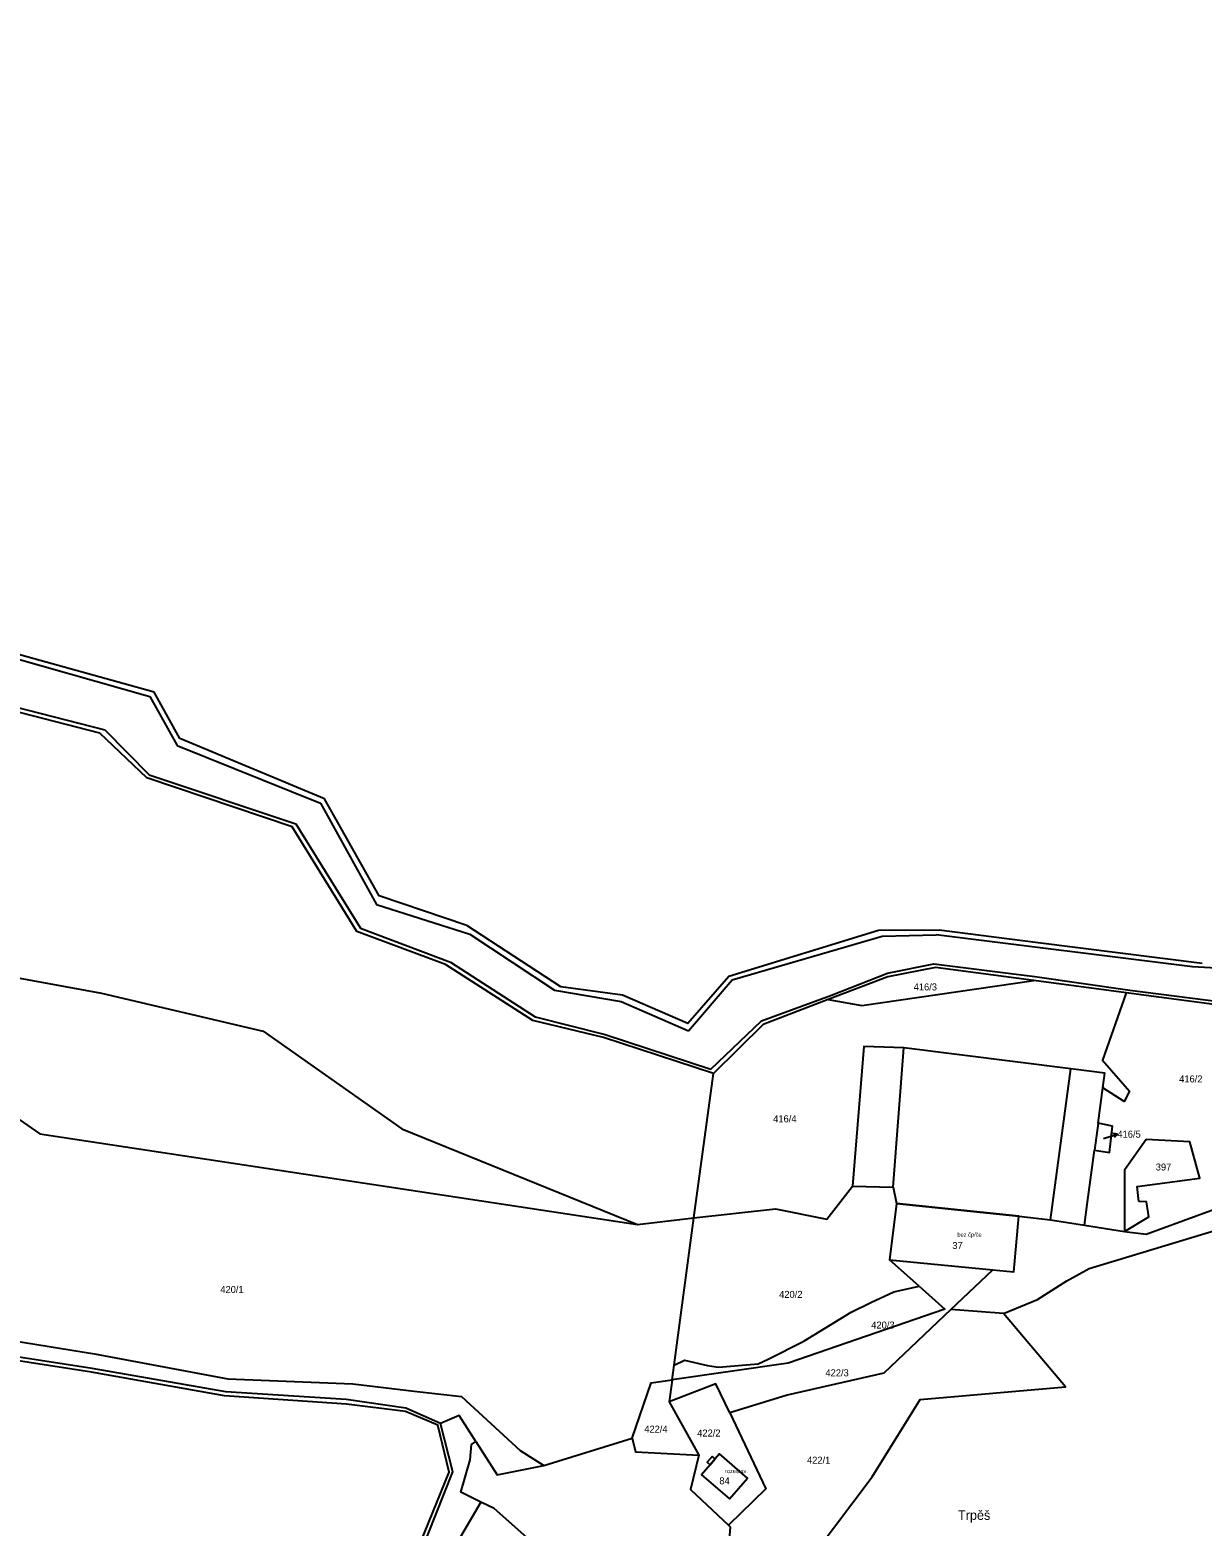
# Model space of a CAD drawing. Extents: x -880531 to -877616, y -1023932 to -1021350.
# Drawn here: x -879800.4 to -879514.7, y -1022591 to -1022226.3 of the extents above; entities that cross this region are included whole.
import ezdxf

# ---------------------------------------------------------------- set-up
doc = ezdxf.new("R2010")
doc.units = 0
for name, color, linetype in [('Definiční body', 7, 'Continuous'), ('Hranice parcel', 7, 'Continuous'), ('Parcelní čísla', 7, 'Continuous'), ('Polygon budovy', 7, 'Continuous'), ('Pop  PČ popisy', 7, 'Continuous'), ('Vnitřní kresba', 7, 'Continuous')]:
    doc.layers.add(name, color=color, linetype=linetype)

msp = doc.modelspace()

# ---------------------------------------------------------------- linework, layer by layer
at = {"layer": 'Hranice parcel'}
for p, q in [((-879763.86, -1022398.98), (-879770.1, -1022387.72)), ((-879728.59, -1022413.68), (-879763.86, -1022398.98)), ((-879670.97, -1022459.53), (-879693.89, -1022444.57)), ((-879578.79, -1022445.71), (-879593.51, -1022445.8)), ((-879554.59, -1022448.77), (-879578.79, -1022445.71)), ((-879514.65, -1022453.82), (-879554.59, -1022448.77)), ((-879555.71, -1022458), (-879579.68, -1022454.82)), ((-879655.97, -1022461.57), (-879670.97, -1022459.53)), ((-879533.14, -1022460.99), (-879555.71, -1022458)), ((-879638.53, -1022515.87), (-879633.8, -1022480.63)), ((-879539.96, -1022492.77), (-879538.83, -1022484.18)), ((-879539.96, -1022492.77), (-879540.85, -1022499.34)), ((-879652.28, -1022517.43), (-879638.53, -1022515.87)), ((-879643.35, -1022551.75), (-879638.53, -1022515.87)), ((-879583.67, -1022532.48), (-879590.9, -1022526.1)), ((-879590.9, -1022526.1), (-879565.68, -1022528.5)), ((-879575.88, -1022538.17), (-879565.68, -1022528.5)), ((-879563.05, -1022539.12), (-879575.88, -1022538.17)), ((-879643.83, -1022555.3), (-879643.35, -1022551.75)), ((-879643.83, -1022555.3), (-879644.55, -1022560.66)), ((-879644.55, -1022560.66), (-879637.31, -1022573.67)), ((-879675.16, -1022576.16), (-879653.62, -1022569.51)), ((-879690.46, -1022585.1), (-879713.01, -1022623.35))]:
    msp.add_line(p, q, dxfattribs=at)
for points in [[(-879633.8, -1022480.63), (-879660.6, -1022471.88), (-879677.81, -1022467.72), (-879699.12, -1022454.05), (-879720.69, -1022446.04), (-879736.48, -1022420.52), (-879771.92, -1022408.58), (-879783.4, -1022397.72), (-879810.92, -1022390.65), (-879838.37, -1022390.91), (-879846.45, -1022372.72), (-879862.92, -1022363.84), (-879883.64, -1022339.68), (-879913.23, -1022324.87), (-879930.34, -1022275.22), (-879914.25, -1022226.31)], [(-879770.1, -1022387.72), (-879811.18, -1022376.32), (-879830.38, -1022382.07), (-879836.8, -1022364.1)], [(-879693.89, -1022444.57), (-879715.3, -1022437.37), (-879728.59, -1022413.68)], [(-879593.51, -1022445.8), (-879630.07, -1022456.98), (-879639.99, -1022468.49), (-879655.97, -1022461.57)], [(-879579.68, -1022454.82), (-879591.23, -1022457.13), (-879605.78, -1022462.66)], [(-879605.78, -1022462.66), (-879597.6, -1022464.07), (-879555.71, -1022458)], [(-879847.14, -1022461.29), (-879797.97, -1022495.32), (-879652.28, -1022517.43)], [(-879605.78, -1022462.66), (-879621.67, -1022468.7), (-879633.8, -1022480.63)], [(-879533.14, -1022460.99), (-879538.93, -1022477.37), (-879532.34, -1022484.94), (-879533.66, -1022487.52), (-879538.83, -1022484.18)], [(-879490.51, -1022467.67), (-879510.53, -1022463.99), (-879533.14, -1022460.99)], [(-879538.83, -1022484.18), (-879538.35, -1022480.6), (-879546.67, -1022479.54), (-879587.34, -1022474.44), (-879597.1, -1022474.1), (-879599.9, -1022508.1)], [(-879540.85, -1022499.34), (-879537.2, -1022499.95), (-879536.53, -1022493.49), (-879539.96, -1022492.77)], [(-879543.35, -1022517.62), (-879542.66, -1022512.62), (-879540.85, -1022499.34)], [(-879530.05, -1022511.88), (-879530.46, -1022508.22), (-879515.2, -1022506.16), (-879517.67, -1022497.29), (-879528.26, -1022496.74), (-879533.58, -1022504.22), (-879533.58, -1022519.17), (-879527.61, -1022515.57), (-879528.19, -1022511.94), (-879530.05, -1022511.88)], [(-879638.53, -1022515.87), (-879618.62, -1022513.62), (-879606.17, -1022516.16), (-879599.9, -1022508.1)], [(-879599.9, -1022508.1), (-879589.98, -1022508.36), (-879589.13, -1022512.34), (-879590.9, -1022526.1)], [(-879563.05, -1022539.12), (-879554.81, -1022535.76), (-879547.63, -1022531.21), (-879542.21, -1022528.17), (-879482.3, -1022510.07)], [(-879543.35, -1022517.62), (-879533.58, -1022519.17), (-879528.32, -1022519.79), (-879503.43, -1022510.75)], [(-879565.68, -1022528.5), (-879560.58, -1022528.99), (-879559.36, -1022515.4), (-879551.61, -1022516.33), (-879543.35, -1022517.62)], [(-879583.67, -1022532.48), (-879577.35, -1022538.06), (-879615.55, -1022551.26), (-879643.83, -1022555.3)], [(-879643.35, -1022551.75), (-879640.86, -1022550.5), (-879635.23, -1022551.85), (-879632.56, -1022552.27), (-879622.84, -1022551.45), (-879620.41, -1022550.3), (-879611.78, -1022545.93), (-879600.23, -1022538.83), (-879595.39, -1022536.5), (-879589.77, -1022533.86), (-879583.67, -1022532.48)], [(-879841.96, -1022539.75), (-879784.65, -1022548.98), (-879752.14, -1022555.09), (-879721.69, -1022556.28), (-879706.73, -1022558.11), (-879695.24, -1022559.41), (-879680.86, -1022572.57), (-879675.16, -1022576.16)], [(-879575.88, -1022538.17), (-879592.27, -1022553.71), (-879615.81, -1022559.05), (-879629.81, -1022563.35)], [(-879623.38, -1022616.52), (-879595.05, -1022578.95), (-879583.42, -1022560.14), (-879547.99, -1022557.04), (-879563.05, -1022539.12)], [(-879700.32, -1022565.93), (-879708.74, -1022562.21), (-879723.29, -1022560.15), (-879752.61, -1022558.22), (-879785.23, -1022552.56), (-879842.49, -1022543.71), (-879866.35, -1022541.91), (-879881.1, -1022540.95)], [(-879653.62, -1022569.51), (-879648.95, -1022556.03), (-879643.83, -1022555.3)], [(-879629.81, -1022563.35), (-879633.16, -1022556.29), (-879644.55, -1022560.66)], [(-879691.7, -1022570.37), (-879695.74, -1022564.05), (-879700.32, -1022565.93)], [(-879629.81, -1022563.35), (-879621.04, -1022581.85), (-879630.14, -1022590.7)], [(-879713.01, -1022623.35), (-879707.48, -1022603.31), (-879697.33, -1022577.75), (-879700.32, -1022565.93)], [(-879690.46, -1022585.1), (-879695.33, -1022582.69), (-879693.09, -1022574.84), (-879692.78, -1022571.11), (-879691.7, -1022570.37)], [(-879691.7, -1022570.37), (-879686.53, -1022578.44), (-879675.16, -1022576.16)], [(-879653.62, -1022569.51), (-879652.78, -1022572.88), (-879637.31, -1022573.67)], [(-879637.31, -1022573.67), (-879639.41, -1022582.07), (-879630.14, -1022590.7)], [(-879625.5, -1022579.31), (-879632.31, -1022573.37), (-879633.35, -1022574.59), (-879634.07, -1022573.97), (-879635.33, -1022575.41), (-879634.6, -1022576.04), (-879636.67, -1022578.45), (-879629.84, -1022584.35), (-879625.5, -1022579.31)], [(-879664.81, -1022605.75), (-879667.6, -1022604.17), (-879687.23, -1022586.69), (-879690.46, -1022585.1)], [(-879630.14, -1022590.7), (-879629.68, -1022591.13), (-879630.98, -1022608.24), (-879627.75, -1022611.76)]]:
    msp.add_lwpolyline(points, dxfattribs=at)
at = {"layer": 'Polygon budovy'}
for points in [[(-879565.68, -1022528.5), (-879560.58, -1022528.99), (-879559.36, -1022515.4), (-879589.13, -1022512.34), (-879590.9, -1022526.1)], [(-879629.84, -1022584.35), (-879625.5, -1022579.31), (-879632.31, -1022573.37), (-879633.35, -1022574.59), (-879634.6, -1022576.04), (-879636.67, -1022578.45)]]:
    msp.add_lwpolyline(points, close=True, dxfattribs=at)
at = {"layer": 'Pop  PČ popisy'}
for p, q in [((-879538.17, -1022496.36), (-879535.316, -1022495.433)), ((-879535.316, -1022495.433), (-879536.423, -1022495.266)), ((-879535.316, -1022495.433), (-879536.114, -1022496.218)), ((-879538.69, -1022496.53), (-879538.17, -1022496.36))]:
    msp.add_line(p, q, dxfattribs=at)
at = {"layer": 'Vnitřní kresba'}
for p, q in [((-879771.18, -1022388.74), (-879764.55, -1022400.69)), ((-879764.55, -1022400.69), (-879729.54, -1022414.79)), ((-879729.54, -1022414.79), (-879715.91, -1022439.43)), ((-879715.91, -1022439.43), (-879693.14, -1022446.71)), ((-879693.14, -1022446.71), (-879672.54, -1022460.35)), ((-879517.02, -1022454.68), (-879579.49, -1022446.85)), ((-879831.44, -1022452.23), (-879783, -1022461.08)), ((-879783, -1022461.08), (-879743.51, -1022470.31)), ((-879672.54, -1022460.35), (-879656.27, -1022463.14)), ((-879656.27, -1022463.14), (-879639.9, -1022470.25)), ((-879743.51, -1022470.31), (-879709.78, -1022494.17)), ((-879589.98, -1022508.36), (-879587.34, -1022474.44)), ((-879551.61, -1022516.33), (-879546.67, -1022479.54)), ((-879709.78, -1022494.17), (-879652.28, -1022517.43)), ((-879589.13, -1022512.34), (-879559.36, -1022515.4)), ((-879634.6, -1022576.04), (-879633.35, -1022574.59))]:
    msp.add_line(p, q, dxfattribs=at)
for points in [[(-879912.42, -1022323.74), (-879882.14, -1022339.39), (-879861.47, -1022363.57), (-879845.41, -1022372.16), (-879837.93, -1022390.13), (-879810.43, -1022389.65), (-879782.15, -1022396.86), (-879771.34, -1022407.84), (-879735.56, -1022419.77), (-879719.82, -1022445.22), (-879697.88, -1022453.49), (-879677.21, -1022466.85), (-879660.2, -1022471.15), (-879634.44, -1022479.57)], [(-879831.15, -1022382.88), (-879811.34, -1022377.43), (-879771.18, -1022388.74)], [(-879639.9, -1022470.25), (-879629.21, -1022457.86), (-879592.66, -1022447.16), (-879579.49, -1022446.85)], [(-879634.44, -1022479.57), (-879622.04, -1022467.8), (-879605.03, -1022461.6), (-879591.35, -1022456.19), (-879580.07, -1022453.96), (-879555.42, -1022456.98), (-879532.25, -1022460.34), (-879509.99, -1022463.2), (-879489.48, -1022467.02)], [(-879461.76, -1022458.04), (-879478.09, -1022458.2), (-879481.7, -1022456.64), (-879517.02, -1022454.68)], [(-879714.02, -1022623.13), (-879708.26, -1022602.63), (-879698.24, -1022577.81), (-879700.94, -1022566.36), (-879708.89, -1022563.02), (-879723.21, -1022561.27), (-879752.94, -1022559.2), (-879785.38, -1022553.47), (-879842.62, -1022544.57)]]:
    msp.add_lwpolyline(points, dxfattribs=at)

# ---------------------------------------------------------------- texts
at = {"layer": 'Definiční body'}
for s, p in [('bez čp/če', (-879574.3, -1022520.44)), ('rozestav.', (-879630.98, -1022578.06))]:
    msp.add_text(s, height=1, dxfattribs=at).set_placement(p)
at = {"layer": 'Parcelní čísla'}
for s, p in [('416/3', (-879584.98, -1022460.41)), ('416/2', (-879520.25, -1022482.83)), ('416/4', (-879619.22, -1022492.54)), ('416/5', (-879535.31, -1022496.3)), ('397', (-879525.96, -1022504.3)), ('37', (-879575.55, -1022523.44)), ('420/1', (-879754, -1022534.14)), ('420/2', (-879617.76, -1022535.34)), ('420/3', (-879595.314, -1022542.81)), ('422/3', (-879606.48, -1022554.45)), ('422/4', (-879650.64, -1022568.18)), ('422/2', (-879637.74, -1022569.13)), ('422/1', (-879610.98, -1022575.75)), ('84', (-879632.34, -1022580.77))]:
    msp.add_text(s, height=1.7, dxfattribs=at).set_placement(p)
at = {"layer": 'Pop  PČ popisy'}
msp.add_text('Trpěš', height=2.3, dxfattribs=at).set_placement((-879574.156, -1022589.44))

doc.saveas('drawing.dxf')
